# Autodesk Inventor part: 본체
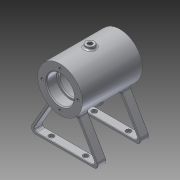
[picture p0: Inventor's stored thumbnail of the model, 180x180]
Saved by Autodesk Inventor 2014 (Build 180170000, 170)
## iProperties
Created: 2016-03
Part Number: 본체
Material: 알루미늄 6061
Document SubType Name: Modeling
Designer: basic
Density: 2.71 g/cm^3
Appearance: 알루미늄 - 평지
Mass: 212.181 g
Surface Area: 337.162 cm^2
Volume: 78.2957 cm^3
Author: basic
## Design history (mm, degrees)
sketch "스케치1"
  geometry: C1 r 26 at (0, 0); 1 further point
  constraints: 1 centre point, 1 coincident
  dimensions: "d0" = 52 diameter of C1
extrude "돌출1" new body sketch "스케치1" distance "d1" = 70; taper "d2" = 0 deg
sketch "스케치2"
  geometry: L1 (26, 70)-(26, 0) reference; L2 (26, 0)-(-26, 0) reference; L3 (-26, 0)-(-26, 70) reference; L4 (-26, 70)-(26, 70) reference; L5 (0, 70)-(0, 0); L6 (16, 70)-(16, 58); L7 (16, 58)-(14, 58); L8 (14, 58)-(14, 56); L9 (14, 56)-(21, 56); L10 (21, 56)-(21, 14); L11 (21, 14)-(14, 14); L12 (14, 14)-(14, 12); L13 (14, 12)-(16, 12); L14 (16, 12)-(16, 0); L15 (26, 35)-(-26, 35)
  constraints: 22 end point, 7 parallel, 3 midpoint, 2 perpendicular, 2 point on line, 1 collinear, 1 other
  dimensions: "d3" = 32 diameter of L6 L5; "d4" = 12 distance between parallel lines of L4 L7; "d5" = 28 diameter of L8 L5; "d7" = 42 distance between parallel lines of L11 L9; "d8" = 12 distance between parallel lines of L2 L13; "d9" = 32 diameter of L14 L5; "d10" = 28 diameter of L12 L5; "d11" = 42 diameter of L10 L5
revolve "회전1" sketch "스케치2" stored, may be unused: angle "d12" = 90 deg
fillet "모깎기1" dims "d13" = 0.3
fillet "모깎기2" dims "d14" = 0.3
node "작업 평면1"
sketch "스케치3"
  geometry: L1 (-16.613, -20)-(-42.594, -65); L2 (-42.594, -65)-(42.594, -65); L3 (42.594, -65)-(16.613, -20); L4 (0, 0)-(0, -65); L5 (-14.183, -21.791)-(-37.398, -62); L6 (-37.398, -62)-(37.398, -62); L7 (37.398, -62)-(14.183, -21.791); C1 r 21 at (0, 0) reference; A1 r 26 centre (0, 0) between (-16.613, -20) and (16.613, -20) reference; 1 further point
  constraints: 14 end point, 4 point on circle, 2 parallel, 2 perpendicular, 1 horizontal, 1 midpoint, 1 other
  dimensions: "d17" = 3 distance between parallel lines of L1 L5; "d18" = 3 distance between parallel lines of L2 L6; "d19" = 3 distance between parallel lines of L3 L7; "d20" = 30 deg angle of L4 L5; "d21" = 30 deg angle of L7 L4 (derived); "d22" = 65 distance from line of L2 point (0, 0); "d23" = 45 distance from line of L2 L3.end
extrude "돌출2" join sketch "스케치3" distance "d24" = 10; taper "d25" = 0 deg
fillet "모깎기3" dims "d26" = 5
fillet "모깎기4" dims "d27" = 3
node "작업 평면3"
node "작업 평면4"
sketch "스케치4"
  geometry: L1 (26, 70)-(-26, 70) reference; C1 r 5 at (0, 35); 2 further points
  constraints: 1 centre point, 1 coincident
  dimensions: "d30" = 35 distance from line of L1 point (0, 35); "d31" = 10 diameter of C1
extrude "돌출3" join sketch "스케치4" distance "d32" = 4; taper "d33" = 0 deg
sketch "스케치5"
  geometry: C1 r 5 at (0, 0) reference; 1 further point
hole "구멍1" sketch "스케치5" at (0, 0) diameter "d34" = 5.188; stored, may be unused: countersink angle "d38" = 90 deg, drill point angle "d40" = 118 deg; dims "d35" = 20, "d36" = 4, "d37" = 2, "d39" = 20
sketch "스케치6"
  geometry: L1 (-5, 25.515)-(-5, 29) reference; L2 (-5, 29)-(-2.594, 29) reference; L3 (-2.594, 29)-(-2.594, 20.839) reference; L4 (2.594, 20.839)-(2.594, 29) reference; L5 (2.594, 29)-(5, 29) reference; L6 (5, 29)-(5, 25.515) reference; L7 (0, 0)-(0, -26); L8 (0, 0)-(7.506, -28.012); A1 r 21 centre (0, 0) between (-2.594, 20.839) and (2.594, 20.839) reference; A2 r 26 centre (0, 0) between (-5, 25.515) and (5, 25.515) reference; 1 further point
  constraints: 4 end point, 1 point on circle
  dimensions: "d42" = 15 deg angle of L7 L8; "d43" = 29 distance of L7.start L8.end
  node "절단 모서리 투영3"
node "작업 평면5"
sketch "스케치7"
  geometry: C1 r 6 at (0, 0); 1 further point
  constraints: 1 centre point
  dimensions: "d44" = 12 diameter of C1
extrude "돌출4" join sketch "스케치7" distance "d45" = 4; taper "d46" = 0 deg
sketch "스케치8"
  geometry: C1 r 6 at (0, 0) reference; 1 further point
sketch "스케치9"
  geometry: C1 r 6 at (0, 0) reference; 1 further point
hole "구멍2" sketch "스케치9" at (0, 0) diameter "d47" = 5.188; stored, may be unused: countersink angle "d51" = 90 deg, drill point angle "d53" = 118 deg; dims "d48" = 20, "d49" = 4, "d50" = 2, "d52" = 20
chamfer "모따기1" distance "d54" = 1; stored, may be unused: second distance "d55" = 2, angle "d56" = 45 deg
sketch "스케치10"
  geometry: L1 (0, -10)-(64.403, -10) reference; L2 (32.202, -10)-(32.202, 55); L3 (-6.315, -10)-(-6.315, 0) reference; L4 (-6.315, 0)-(0, 0) reference; L5 (0, 0)-(0, -10) reference; L6 (64.403, -10)-(0, -10) reference; L7 (64.403, 0)-(64.403, -10) reference; L8 (64.403, 0)-(70.718, 0) reference; L9 (70.718, 0)-(70.718, -10) reference; L10 (70.718, -10)-(64.403, -10) reference; L11 (0, -10)-(-6.315, -10) reference; L12 (0, 0)-(64.403, 0) reference; L13 (-6.315, 40)-(-6.315, 50) reference; L14 (-6.315, 50)-(0, 50) reference; L15 (0, 50)-(0, 40) reference; L16 (64.403, 40)-(0, 40) reference; L17 (64.403, 50)-(64.403, 40) reference; L18 (64.403, 50)-(70.718, 50) reference; L19 (70.718, 50)-(70.718, 40) reference; L20 (70.718, 40)-(64.403, 40) reference; L21 (0, 40)-(-6.315, 40) reference; L22 (0, 50)-(64.403, 50) reference; 4 further points
  constraints: 2 end point, 2 symmetric about line, 1 midpoint, 1 perpendicular
  dimensions: "d59" = 40 distance of point (52.202, -5) point (12.202, -5); "d60" = 40 distance of point (52.202, 45) point (12.202, 45); "d61" = 20 distance from line of point (12.202, 45) L2 (derived)
hole "구멍3" sketch "스케치10" at (12.202, -5), (52.202, -5), (12.202, 45), (52.202, 45) diameter "d62" = 6; stored, may be unused: countersink angle "d66" = 90 deg, drill point angle "d68" = 118 deg; dims "d63" = 20, "d64" = 4, "d65" = 2, "d67" = 4
fillet "모깎기5" dims "d69" = 0.5
sketch "스케치11" dims "d70" = 42
  geometry: C1 r 17 at (0, 0) reference; 2 further points
  constraints: 1 coincident, 1 vertical alignment, 2 other
hole "구멍4" sketch "스케치11" at (0, 21) diameter "d71" = 3.242; stored, may be unused: countersink angle "d75" = 90 deg, drill point angle "d77" = 118 deg; dims "d72" = 8, "d73" = 4, "d74" = 2, "d76" = 10
node "작업 평면6"
sketch "스케치12"
  geometry: L1 (-26, 0)-(-26, 70) reference; 2 further points
  constraints: 1 other
  dimensions: "d82" = 35 distance of point (0, 0) point (0, 35); "d83" = 26 distance from line of L1 point (0, 35)
feature "엠보싱1" sketch "스케치12" dims "d84" = 0.5, "d85" = 0
fillet "모깎기6" dims "d86" = 2
fillet "모깎기8" dims "d88" = 2, "d89" = 3
node "솔리드1"
mirror "대칭1"
pattern_circular "원형 패턴1" dims angle "d79" = 360 deg
mirror "대칭2"
node "절단 모서리 투영1"
node "절단 모서리 투영2"
node "절단 모서리 투영4"
other parameters: "d15" = 15, "d28" = 35, "d29" = 29, "d81" = -27
